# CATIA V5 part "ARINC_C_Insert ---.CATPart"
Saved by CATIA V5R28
Part number: ARINC_C_INSERT
Revision: ---
Publications: "Logical Termination.1", "Logical Pin.1", "CaCP", "Face_generated(CaCP)", "Axis_generated(CaCP)", "Face_generated(CaCP).1", "BCP", "BCPRPoint_generated(BCP)", "BCPCPlane_generated(BCP)"
Bounding box of the stored display mesh (mm): x 0 to 32.842, y -13.424 to 13.424, z -14.059 to 14.059
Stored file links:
  C:\Users\ajc8720\Documents\BOEING_WORK\0001-2CES\004-AP242\Boeing-Generic_Harness_R3\ARINC_C_Insert ---.CATPart
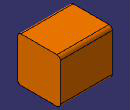
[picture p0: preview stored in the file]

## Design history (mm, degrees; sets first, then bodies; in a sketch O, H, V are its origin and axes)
Parameters
  PartNumber = "BACC66H_C_Insert"
  InsertLength = 32.8422 mm
  InsertHeight = 28.1178 mm
  InsertWidth = 26.8478 mm
  EdgeRadius = 2.1082 mm
  PubWorkaround = "DONE"
Set1 "EGFOBody"
  Set2 "CaCPOBody"
    Point1 "CaCPRPoint": (0, 0, 0)
    Plane1 "CaCPCPlane": type OffsetPt, RefPlane yz-plane, RefPoint Point1
  Set3 "BCPOBody"
    Point2 "BCPRPoint": (32.8422 {= InsertLength}, 0, 0)
    Plane2 "BCPCPlane": type OffsetPt, RefPlane yz-plane, RefPoint Point2
Body1 (main body)
  Sketch1 on yz-plane, origin (0, 0, 0), H (0, 1, 0), V (0, 0, 1)
    line L1 (-11.3157, 14.0589) -> (11.3157, 14.0589)
    line L2 (13.4239, 11.9507) -> (13.4239, -11.9507)
    line L3 (11.3157, -14.0589) -> (-11.3157, -14.0589)
    line L4 (-13.4239, -11.9507) -> (-13.4239, 11.9507)
    arc A1 centre (-11.3157, 11.9507) radius 2.1082 from (-13.4239, 11.9507) to (-11.3157, 14.0589) cw
    arc A2 centre (11.3157, 11.9507) radius 2.1082 from (11.3157, 14.0589) to (13.4239, 11.9507) cw
    arc A3 centre (-11.3157, -11.9507) radius 2.1082 from (-13.4239, -11.9507) to (-11.3157, -14.0589) ccw
    arc A4 centre (11.3157, -11.9507) radius 2.1082 from (11.3157, -14.0589) to (13.4239, -11.9507) ccw
    radius A1 = 2.1082 {= EdgeRadius}
    radius A2 = 2.1082 {= EdgeRadius}
    radius A3 = 2.1082 {= EdgeRadius}
    radius A4 = 2.1082 {= EdgeRadius}
    distance L1 L3 = 28.1178 {= InsertHeight}
    distance L2 L4 = 26.8478 {= InsertWidth}
    horizontal: L1 H, L3 H
    vertical: L2 V, L4 V
    symmetry: L1 L3 H, L4 L2 V
    tangency: A1 L4, A1 L1, A2 L1, A2 L2, A3 L4, A3 L3, A4 L3, A4 L2
  Pad1: profile Sketch1, direction (1, 0, 0), length 32.8422 {= InsertLength}
Body2 "Male Cherbourg-CaCP"
  Sketch2 "Sketch.2" on Plane1, origin (0, 0, 0), H (0, 1, 0), V (0, 0, 1)
    line L1 (-0.672, 0.762) -> (0.672, 0.762)
    point P1 (-0.672, 0.762)
    point P2 (0.672, 0.762)
    arc A1 centre (0, 0) radius 1.016 from (-1.016, 0) to (1.016, 0) ccw
    point P3 (0, 0)
    point P4 (-1.016, 0)
    point P5 (1.016, 0)
    reference projected point E1 (0, 0)
    arc A2 centre (0, 0) radius 1.016 from (1.016, 0) to (0.672, 0.762) ccw
    point P6 (0, 0)
    point P7 (1.016, 0)
    point P8 (0.672, 0.762)
    arc A3 centre (0, 0) radius 1.016 from (-0.672, 0.762) to (-1.016, 0) ccw
    point P9 (0, 0)
    point P10 (-0.672, 0.762)
    point P11 (-1.016, 0)
    reference projected point E2 (0, 0)
    reference projected point E3 (0, 0)
    length L1 = 1.344
    radius A1 = 1.016
    radius A3 = 1.016
    radius A2 = 1.016
    distance L1 P5 = 0.762
    distance P4 L1 = 0.762
    distance P7 L1 = 0.762
    distance P11 L1 = 0.762
    coincidence: P3 E1, P6 E2, P9 E3, P8 P2, P10 P1
    horizontal: L1 H
  Pad2: profile Sketch2, direction (1, 0, 0), length 0.508, opposite side up to Plane1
